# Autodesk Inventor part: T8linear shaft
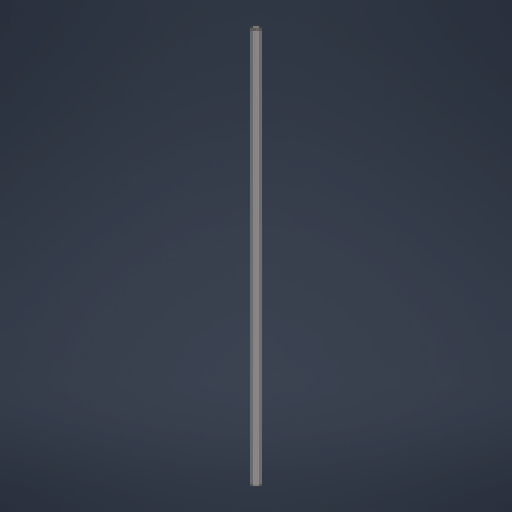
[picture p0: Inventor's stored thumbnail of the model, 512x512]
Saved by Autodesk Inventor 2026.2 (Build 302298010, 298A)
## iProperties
Created: 2026-04
Part Number: T8linear shaft
Material: 스테인리스스틸
Document SubType Name: Modeling
Designer: work
Density: 8 g/cm^3
Appearance: 반연마
Author: work
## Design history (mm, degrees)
sketch "스케치1"
  geometry: C1 r 4 at (0, 0); 1 further point
  constraints: 1 centre point, 1 coincident
  dimensions: "d0" = 8 diameter of C1
extrude "돌출1" new body sketch "스케치1" distance "d1" = 450; taper "d2" = 0 deg
chamfer "모따기1" distance "d3" = 1; stored, may be unused: second distance "d4" = 2, angle "d5" = 45 deg
node "솔리드1"
